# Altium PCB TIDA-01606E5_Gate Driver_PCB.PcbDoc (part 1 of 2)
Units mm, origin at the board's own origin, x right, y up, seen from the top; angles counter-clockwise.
Board outline 135 x 43 mm, 4 copper layers (Top Layer, GND, PWR, Bottom Layer), stack 1.59 mm thick; 184 components, 90 nets, 537 pads, 139 vias.
Unrouted connection lines stored in the file: 48.
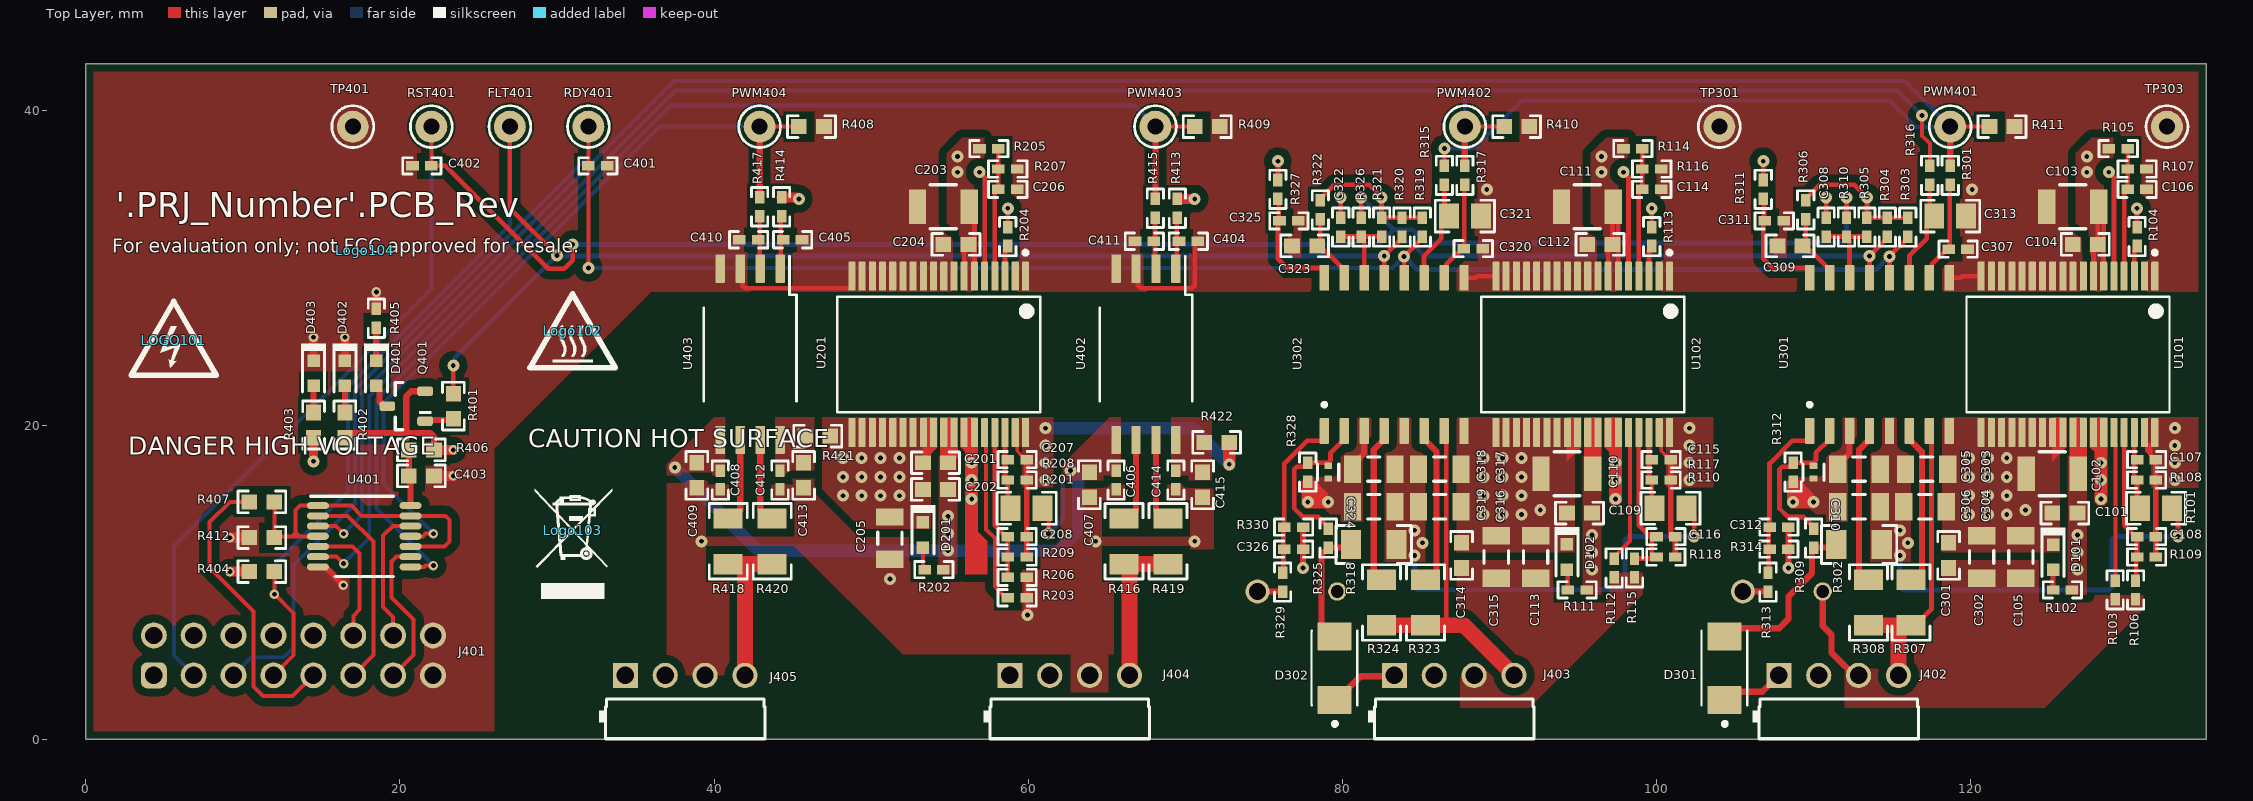
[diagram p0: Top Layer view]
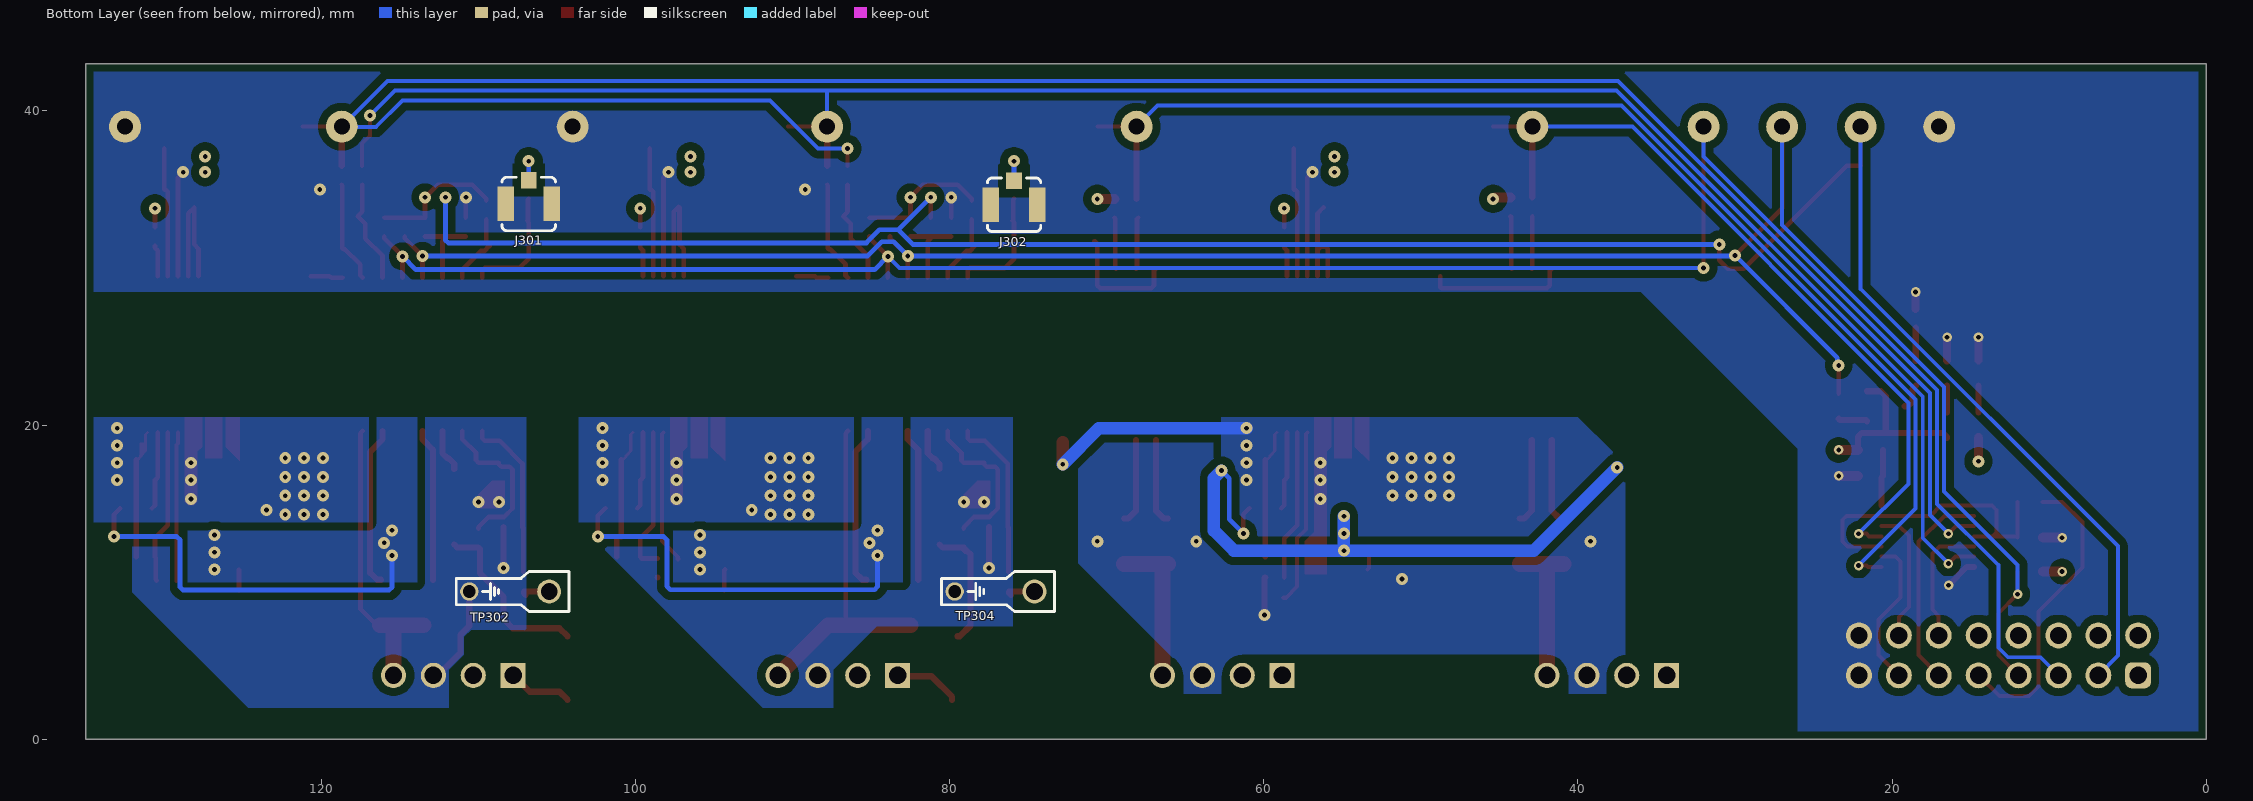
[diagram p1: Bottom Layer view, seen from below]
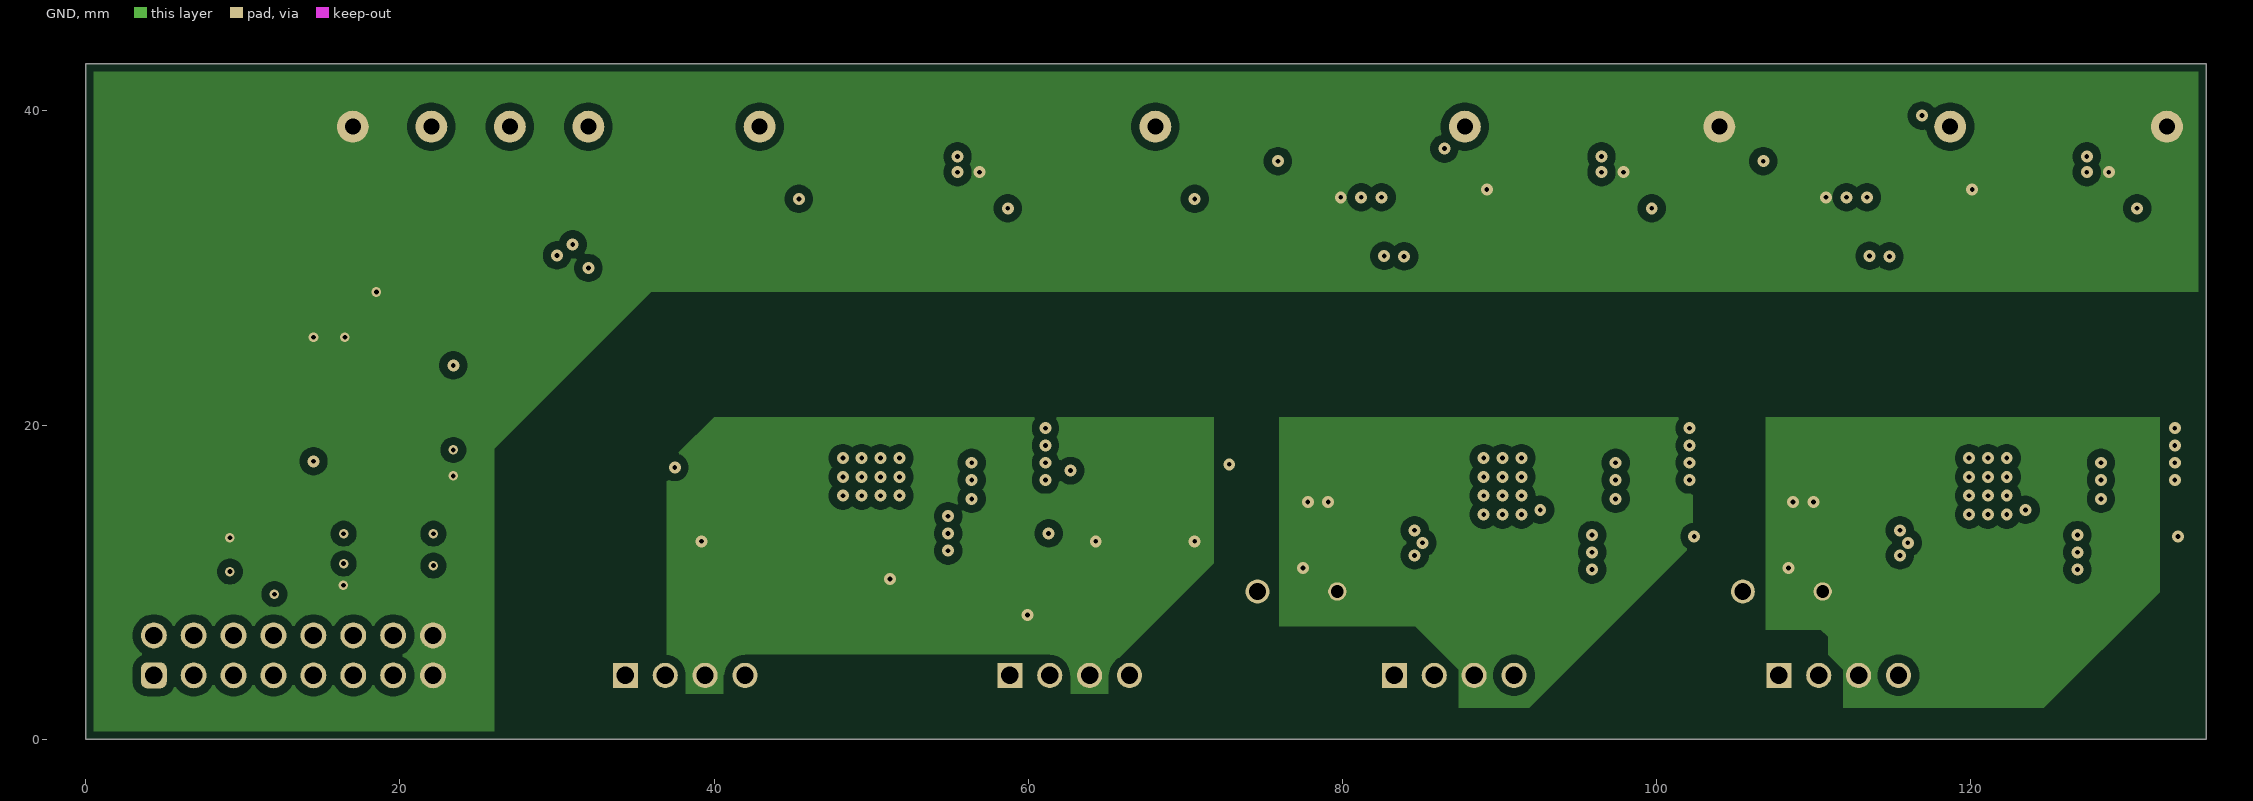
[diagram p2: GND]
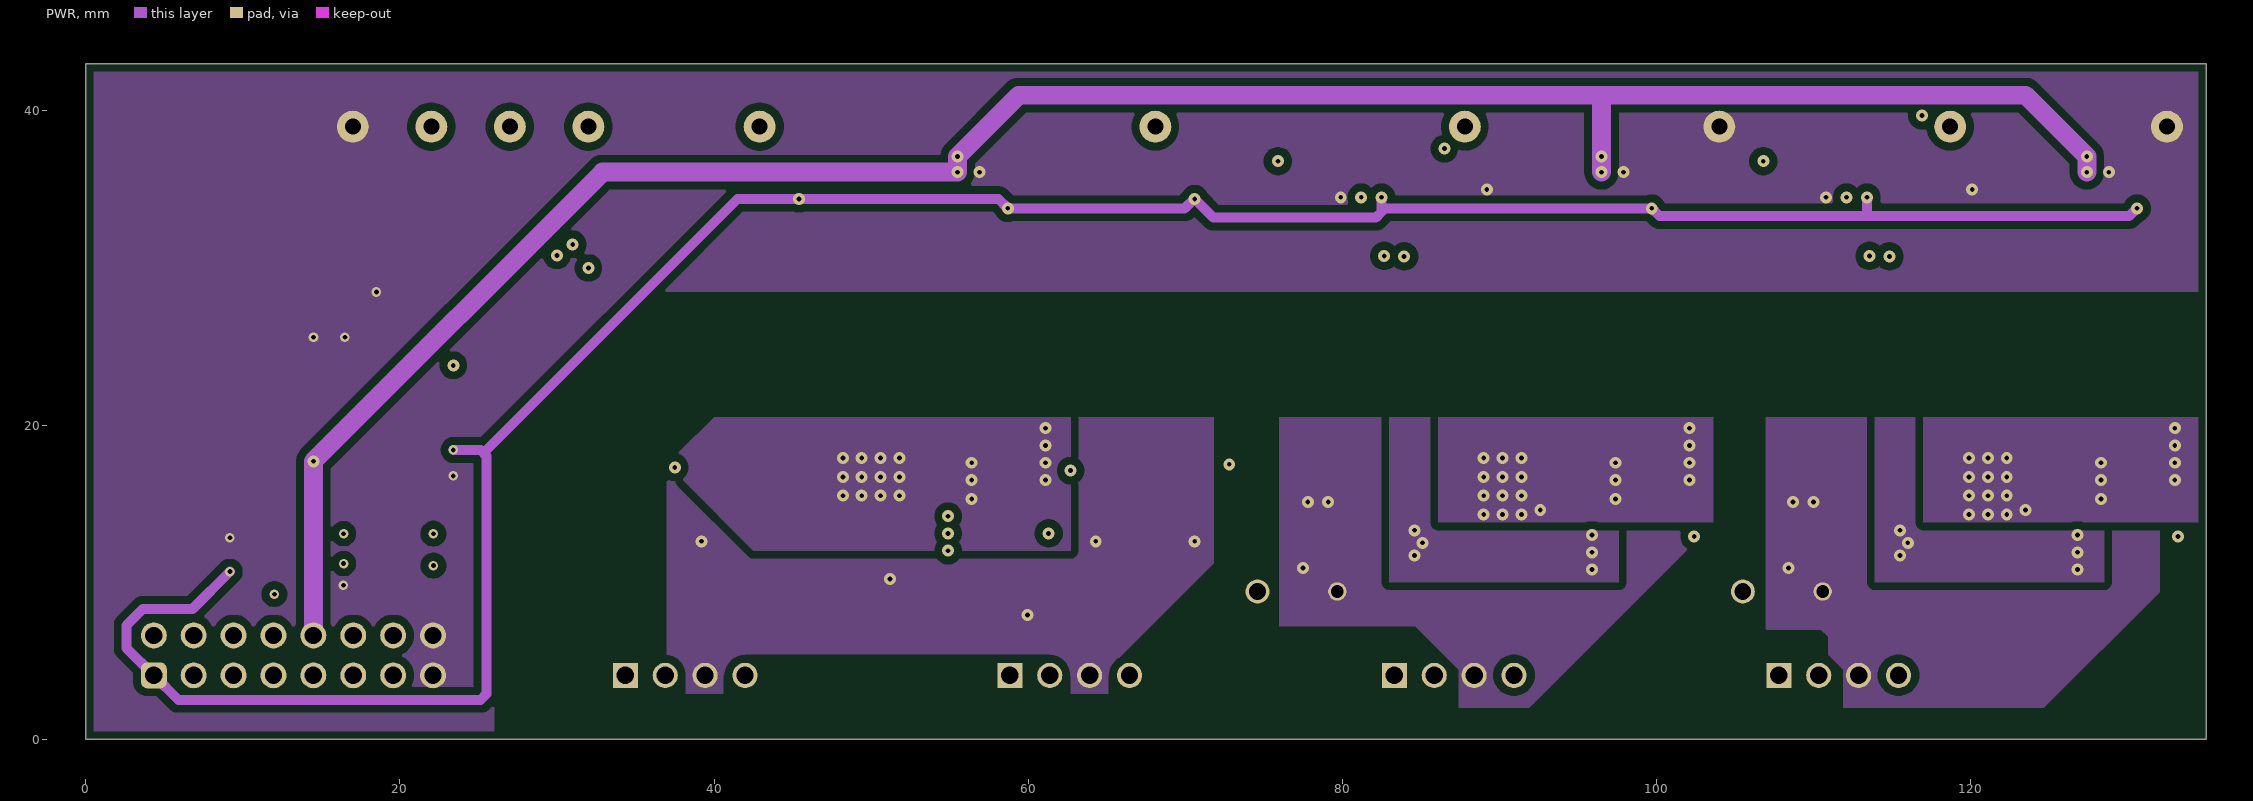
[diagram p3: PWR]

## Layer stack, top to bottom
Top Solder: solder mask 0.0102, Solder Resist, Dk 3.5
Top Layer: signal copper 0.0356
Dielectric1: core 0.5588, FR-4 High Tg, Dk 4.2
GND: signal copper 0.0356
Dielectric 2: prepreg 0.3302, FR-4 High Tg, Dk 4.2
PWR: signal copper 0.0356
Dielectric 3: core 0.5588, FR-4 High Tg, Dk 4.2
Bottom Layer: signal copper 0.0356
Bottom Solder: solder mask 0.0102, Solder Resist, Dk 3.5

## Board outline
0,0 135,0 135,43 0,43

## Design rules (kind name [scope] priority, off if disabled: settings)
AcuteAngle [All] p1: minimum=4.50000000000000E+0001 checktracksonly=FALSE
AssemblyTestPointUsage [All] p1: valid=2
Clearance Clearance_2 [InNetClass('HV') vs Not InNetClass('HV')] p1: gap=1.524 ignorepadtopadclearanceinfootprint=FALSE
Clearance Clearance_1 [InNetClass('MV') vs Not InNetClass('MV')] p2: gap=0.762 ignorepadtopadclearanceinfootprint=FALSE
Clearance Clearance_Keepouts [((IsTrack Or IsArc) And Not InPoly) And IsFree and IsKeepOut vs ((IsTrack Or IsArc) And Not InPoly) And IsFree and IsKeepOut] p3: gap=0 ignorepadtopadclearanceinfootprint=FALSE
Clearance Clearance_BoardEdge_MountingHoles [OnCopper and InComponentClass('Mounting Holes') vs IsKeepOut] p4: gap=1.016 ignorepadtopadclearanceinfootprint=FALSE except(0: Arc-Hole Track-Hole SMDPad-Hole THPad-Hole Via-Hole Fill-Hole Poly-Hole Region-Hole Text-Hole)
Clearance Clearance_BoardEdge_Poly [OnCopper and InPoly vs IsKeepOut] p5: gap=0.635 ignorepadtopadclearanceinfootprint=FALSE except(0: Arc-Hole Track-Hole SMDPad-Hole THPad-Hole Via-Hole Fill-Hole Poly-Hole Region-Hole Text-Hole)
Clearance Clearance_BoardEdge [OnCopper and Not InComponentClass('Logo') and not InComponentClass('FiducialMark') and not InRegion(1000,500,4000,800) and Not IsKeepout vs IsKeepOut] p6: gap=1.905 ignorepadtopadclearanceinfootprint=FALSE except(0: Arc-Hole Track-Hole SMDPad-Hole THPad-Hole Via-Hole Fill-Hole Poly-Hole Region-Hole Text-Hole)
Clearance Clearance_Poly [InPolygon] p7: gap=0.508 ignorepadtopadclearanceinfootprint=FALSE except(0: Arc-Hole Track-Hole SMDPad-Hole THPad-Hole Via-Hole Fill-Hole Poly-Hole Region-Hole Text-Hole)
Clearance [All] p8: gap=0.2 ignorepadtopadclearanceinfootprint=FALSE except(0: Arc-Hole Track-Hole SMDPad-Hole THPad-Hole Via-Hole Fill-Hole Poly-Hole Region-Hole Text-Hole)
ComponentClearance ComponentClearance_MountingHoles_FiducialMarks [InComponentClass('Mounting Holes') vs InComponentClass('FiducialMark')] p1: gap=0.508 collisioncheckmode=3 verticalgap=0.254 showdistances=FALSE
ComponentClearance ComponentClearance_Shunt [InComponentClass('Header') vs InComponentClass('Shunt')] p2: gap=0 collisioncheckmode=3 verticalgap=0 showdistances=FALSE
ComponentClearance ComponentClearance_Logo [InComponentClass('Logo')] p3: gap=0.127 collisioncheckmode=3 verticalgap=0.254 showdistances=FALSE
ComponentClearance ComponentClearance_ScrewToNut [(HasFootprint('NY PMS 440 0025 PH')) vs (HasFootprint('Keystone_1902C'))] p4: gap=0.508 collisioncheckmode=3 verticalgap=2540 showdistances=FALSE
ComponentClearance ComponentClearance_MountingHoles [InComponentClass('Mounting Holes')] p5: gap=0.508 collisioncheckmode=3 verticalgap=0.254 showdistances=FALSE
ComponentClearance ComponentClearance_SmallPassives [HasFootprint('0201*') or HasFootprint('0402*') or HasFootprint('0508') or HasFootprint('0603*') or HasFootprint('0612') or HasFootprint('0805*') or HasFootprint('0815*') or HasFootprint('0830*') or HasFootprint('1206*') or HasFootprint('1210*') or HasFootprint('1808*') or HasFootprint('1812*') or HasFootprint('1825*') or HasFootprint('2010*') or HasFootprint('2220*') or HasFootprint('2225*') or HasFootprint('2512*') or HasFootprint('2728*') or HasFootprint('3518*') vs HasFootprint('0201*') or HasFootprint('0402*') or HasFootprint('0508') or HasFootprint('0603*') or HasFootprint('0612') or HasFootprint('0805*') or HasFootprint('0815*') or HasFootprint('0830*') or HasFootprint('1206*') or HasFootprint('1210*') or HasFootprint('1808*') or HasFootprint('1812*') or HasFootprint('1825*') or HasFootprint('2010*') or HasFootprint('2220*') or HasFootprint('2225*') or HasFootprint('2512*') or HasFootprint('2728*') or HasFootprint('3518*')] p6: gap=0.508 collisioncheckmode=3 verticalgap=0.508 showdistances=FALSE
ComponentClearance ComponentClearance_THtoSMT [IsThruComponent vs IsSMTComponent] p7: gap=0.254 collisioncheckmode=3 verticalgap=0.254 showdistances=FALSE
ComponentClearance ComponentClearance_THtoTH [IsThruComponent vs IsThruComponent] p8: gap=0.254 collisioncheckmode=3 verticalgap=0.254 showdistances=FALSE
ComponentClearance [All] p9: gap=0.254 collisioncheckmode=3 verticalgap=0.254 showdistances=FALSE
DiffPairsRouting [All] p1: maxlimit=2.54 minlimit=0.254 mostfreqgap=0.254 toplayer_minwidth=0.381 toplayer_maxwidth=0.381 toplayer_prefwidth=0.381 midlayer1_minwidth=0.381 midlayer1_maxwidth=0.381 midlayer1_prefwidth=0.381 midlayer2_minwidth=0.381 midlayer2_maxwidth=0.381 midlayer2_prefwidth=0.381 bottomlayer_minwidth=0.381 bottomlayer_maxwidth=0.381 bottomlayer_prefwidth=0.381 maxuncoupledlength=25.4
FabricationTestPointUsage TestPointUsage [All] p1: valid=2 allowmultiple=FALSE
FabricationTestpoint Testpoint [All] p1: side=3 testpointundercomponent=TRUE minsize=1.016 maxsize=2.54 preferedsize=1.524 minholesize=0 maxholesize=1.016 preferedholesize=0.813 testpointgrid=0.025 allowsidetop=TRUE allowsidebottom=TRUE usegrid=TRUE gridtolerance=0
FanoutControl Fanout_LCC [IsLCC] p1: bgadir=Out bgaviamode=Centered fanoutstyle=Auto fanoutdirection=Alternating viagrid=0.025 // Fanout_LCC (Default Rule)
FanoutControl Fanout_BGA [IsBGA] p2: bgadir=Out bgaviamode=Centered fanoutstyle=Auto fanoutdirection=Alternating viagrid=0.025 // Fanout_BGA (Default Rule)
FanoutControl Fanout_Default [All] p4: bgadir=Out bgaviamode=Centered fanoutstyle=Auto fanoutdirection=Alternating viagrid=0.025 // Fanout_Default (Default Rule)
FanoutControl Fanout_Small [(CompPinCount < 5)] p5: bgadir=Out bgaviamode=Centered fanoutstyle=Auto fanoutdirection=OutThenIn viagrid=0.025 // Fanout_Small (Default Rule)
Height [All] p1: minheight=0 maxheight=76.2 prefheight=12.7
HoleSize [All] p1: absolutevalues=TRUE maxlimit=6.375 minlimit=0.178 maxpercent=80.000 minpercent=20.000
MinimumAnnularRing MinimumAnnularRing_ThermalPadVias [IsVia and InAnyComponent] p1: minimumring=0.15
MinimumAnnularRing [All] p2: minimumring=0.124
MinimumSolderMaskSliver MinimumSolderMaskSliver_Logo [InComponentClass('Logo') vs InComponentClass('Logo')] p1: minsoldermaskwidth=0.018
MinimumSolderMaskSliver [All] p2: minsoldermaskwidth=0.051
PlaneConnect [All] p1: planeconnectstyle=Direct reliefexpansion=0.254 reliefentries=4 reliefconductorwidth=0.254 reliefairgap=0.254
PolygonConnect PolygonConnect_15 [All vs IsNamedPolygon('C109_2') Or  IsNamedPolygon('C107_2') Or  IsNamedPolygon('HV') Or  IsNamedPolygon('Q203_5') Or  IsNamedPolygon('C107_2') Or  IsNamedPolygon('HS') Or  IsNamedPolygon('Q201_5') Or  IsNamedPolygon('Q203_5') Or  IsNamedPolygon('C106_2') Or  IsNamedPolygon('C108_2') Or  IsNamedPolygon('Vout') Or  IsNamedPolygon('Q203_5') Or  IsNamedPolygon('C108_2') Or  IsNamedPolygon('C113_2') Or  IsNamedPolygon('Q203_5') Or  IsNamedPolygon('Q201_5') Or  IsNamedPolygon('C107_2') Or  IsNamedPolygon('C102_1') Or  IsNamedPolygon('SGND') Or  IsNamedPolygon('GND') Or  IsNamedPolygon('SGND') Or  IsNamedPolygon('GND') Or  IsNamedPolygon('IN+') Or  IsNamedPolygon('IN+') Or  IsNamedPolygon('Q201_5') Or  IsNamedPolygon('Q201_5') Or  IsNamedPolygon('SGND') Or  IsNamedPolygon('SGND') Or  IsNamedPolygon('Vout') Or  IsNamedPolygon('Vout') Or  IsNamedPolygon('IN+') Or  IsNamedPolygon('GND') Or  IsNamedPolygon('IN+') Or  IsNamedPolygon('GND')] p1: connectstyle=Direct reliefconductorwidth=0.254 reliefentries=4 polygonreliefangle="90 Angle" airgapwidth=0.254
PolygonConnect PolygonConnect_14 [All vs IsNamedPolygon('C106_2') Or  IsNamedPolygon('C107_2') Or  IsNamedPolygon('C107_2') Or  IsNamedPolygon('C107_2') Or  IsNamedPolygon('C102_1') Or  IsNamedPolygon('Q203_5') Or  IsNamedPolygon('Vout') Or  IsNamedPolygon('Q203_5') Or  IsNamedPolygon('Q203_5') Or  IsNamedPolygon('Q201_5') Or  IsNamedPolygon('C108_2') Or  IsNamedPolygon('Q203_5') Or  IsNamedPolygon('HS') Or  IsNamedPolygon('HV') Or  IsNamedPolygon('C108_2') Or  IsNamedPolygon('Q201_5') Or  IsNamedPolygon('C109_2') Or  IsNamedPolygon('Q201_5') Or  IsNamedPolygon('Q201_5') Or  IsNamedPolygon('C113_2')] p2: connectstyle=Direct reliefconductorwidth=0.254 reliefentries=4 polygonreliefangle="90 Angle" airgapwidth=0.254
PolygonConnect PolygonConnect_13 [All vs IsNamedPolygon('C102_1') Or  IsNamedPolygon('HV') Or  IsNamedPolygon('C107_2') Or  IsNamedPolygon('C109_2') Or  IsNamedPolygon('C107_2') Or  IsNamedPolygon('C108_2') Or  IsNamedPolygon('C106_2') Or  IsNamedPolygon('C108_2') Or  IsNamedPolygon('C113_2') Or  IsNamedPolygon('C107_2')] p3: connectstyle=Direct reliefconductorwidth=0.254 reliefentries=4 polygonreliefangle="90 Angle" airgapwidth=0.254
PolygonConnect PolygonConnect_12 [All vs IsNamedPolygon('C107_2') Or  IsNamedPolygon('C113_2') Or  IsNamedPolygon('C106_2') Or  IsNamedPolygon('C107_2') Or  IsNamedPolygon('C107_2') Or  IsNamedPolygon('C102_1')] p4: connectstyle=Direct reliefconductorwidth=0.254 reliefentries=4 polygonreliefangle="90 Angle" airgapwidth=0.254
PolygonConnect PolygonConnect_11 [All vs IsNamedPolygon('C106_2') Or  IsNamedPolygon('C102_1') Or  IsNamedPolygon('C107_2') Or  IsNamedPolygon('C107_2') Or  IsNamedPolygon('C107_2')] p5: connectstyle=Direct reliefconductorwidth=0.254 reliefentries=4 polygonreliefangle="90 Angle" airgapwidth=0.254
PolygonConnect PolygonConnect_10 [All vs IsNamedPolygon('C106_2')] p6: connectstyle=Direct reliefconductorwidth=0.254 reliefentries=4 polygonreliefangle="90 Angle" airgapwidth=0.254
PolygonConnect PolygonConnect_9 [All vs IsNamedPolygon('C11_1') Or  IsNamedPolygon('Vin') Or  IsNamedPolygon('Vin') Or  IsNamedPolygon('5V') Or  IsNamedPolygon('D6_2') Or  IsNamedPolygon('Q3_3') Or  IsNamedPolygon('GND2') Or  IsNamedPolygon('GND2') Or  IsNamedPolygon('GND') Or  IsNamedPolygon('Q3_4') Or  IsNamedPolygon('12V5') Or  IsNamedPolygon('GND') Or  IsNamedPolygon('12V5') Or  IsNamedPolygon('D3_1')] p7: connectstyle=Direct reliefconductorwidth=0.254 reliefentries=4 polygonreliefangle="90 Angle" airgapwidth=0.254
PolygonConnect PolygonConnect_8 [All vs IsNamedPolygon('C11_1') Or  IsNamedPolygon('Vin') Or  IsNamedPolygon('12V5') Or  IsNamedPolygon('Q3_3') Or  IsNamedPolygon('GND2') Or  IsNamedPolygon('GND2') Or  IsNamedPolygon('5V') Or  IsNamedPolygon('Q3_4') Or  IsNamedPolygon('12V5')] p8: connectstyle=Direct reliefconductorwidth=0.254 reliefentries=4 polygonreliefangle="90 Angle" airgapwidth=0.254
PolygonConnect PolygonConnect_7 [All vs IsNamedPolygon('GND2') Or  IsNamedPolygon('GND2') Or  IsNamedPolygon('5V') Or  IsNamedPolygon('12V5') Or  IsNamedPolygon('12V5') Or  IsNamedPolygon('C11_1')] p9: connectstyle=Direct reliefconductorwidth=0.254 reliefentries=4 polygonreliefangle="90 Angle" airgapwidth=0.254
PolygonConnect PolygonConnect_6 [All vs IsNamedPolygon('GND2') Or  IsNamedPolygon('SGND') Or  IsNamedPolygon('GND1') Or  IsNamedPolygon('C901_1') Or  IsNamedPolygon('SGND') Or  IsNamedPolygon('GND2') Or  IsNamedPolygon('GND1')] p10: connectstyle=Direct reliefconductorwidth=0.254 reliefentries=4 polygonreliefangle="90 Angle" airgapwidth=0.254
PolygonConnect PolygonConnect_5 [All vs IsNamedPolygon('GND1') Or  IsNamedPolygon('GND1')] p11: connectstyle=Direct reliefconductorwidth=0.254 reliefentries=4 polygonreliefangle="90 Angle" airgapwidth=0.254
PolygonConnect PolygonConnect_4 [All vs IsNamedPolygon('C21_1') Or  IsNamedPolygon('C5_1') Or  IsNamedPolygon('C12_2') Or  IsNamedPolygon('C2_2') Or  IsNamedPolygon('C13_1') Or  IsNamedPolygon('C28_1') Or  IsNamedPolygon('C6_1') Or  IsNamedPolygon('GND') Or  IsNamedPolygon('GND2') Or  IsNamedPolygon('C14_1') Or  IsNamedPolygon('C13_1') Or  IsNamedPolygon('Q1_3') Or  IsNamedPolygon('C14_1') Or  IsNamedPolygon('C5_1') Or  IsNamedPolygon('GND2') Or  IsNamedPolygon('C28_1') Or  IsNamedPolygon('D5_2') Or  IsNamedPolygon('D6_2') Or  IsNamedPolygon('D2_1') Or  IsNamedPolygon('C12_2') Or  IsNamedPolygon('D2_1') Or  IsNamedPolygon('C4_1') Or  IsNamedPolygon('C4_1') Or  IsNamedPolygon('C2_2') Or  IsNamedPolygon('GND') Or  IsNamedPolygon('C33_1') Or  IsNamedPolygon('C9_1')] p12: connectstyle=Direct reliefconductorwidth=0.254 reliefentries=4 polygonreliefangle="90 Angle" airgapwidth=0.254
PolygonConnect PolygonConnect_3 [All vs IsNamedPolygon('C28_1') Or  IsNamedPolygon('C12_2') Or  IsNamedPolygon('C28_1') Or  IsNamedPolygon('C9_1') Or  IsNamedPolygon('D5_2') Or  IsNamedPolygon('C12_2') Or  IsNamedPolygon('C2_2') Or  IsNamedPolygon('C14_1') Or  IsNamedPolygon('C4_1') Or  IsNamedPolygon('C14_1') Or  IsNamedPolygon('D6_2') Or  IsNamedPolygon('GND2') Or  IsNamedPolygon('Q1_3') Or  IsNamedPolygon('C5_1') Or  IsNamedPolygon('D2_1') Or  IsNamedPolygon('C4_1') Or  IsNamedPolygon('C13_1') Or  IsNamedPolygon('C5_1') Or  IsNamedPolygon('C13_1') Or  IsNamedPolygon('C33_1') Or  IsNamedPolygon('D2_1') Or  IsNamedPolygon('GND') Or  IsNamedPolygon('GND') Or  IsNamedPolygon('GND2') Or  IsNamedPolygon('C2_2') Or  IsNamedPolygon('C6_1') Or  IsNamedPolygon('C21_1')] p13: connectstyle=Direct reliefconductorwidth=0.254 reliefentries=4 polygonreliefangle="90 Angle" airgapwidth=0.254
PolygonConnect PolygonConnect_2 [All vs IsNamedPolygon('C21_1') Or  IsNamedPolygon('C4_1') Or  IsNamedPolygon('D5_2') Or  IsNamedPolygon('C5_1') Or  IsNamedPolygon('C14_1') Or  IsNamedPolygon('C13_1') Or  IsNamedPolygon('C4_1') Or  IsNamedPolygon('C33_1') Or  IsNamedPolygon('C12_2') Or  IsNamedPolygon('D2_1') Or  IsNamedPolygon('C2_2') Or  IsNamedPolygon('C28_1') Or  IsNamedPolygon('C12_2') Or  IsNamedPolygon('D2_1') Or  IsNamedPolygon('C5_1') Or  IsNamedPolygon('Q1_3') Or  IsNamedPolygon('GND') Or  IsNamedPolygon('D6_2') Or  IsNamedPolygon('C6_1') Or  IsNamedPolygon('C2_2') Or  IsNamedPolygon('C14_1') Or  IsNamedPolygon('C28_1') Or  IsNamedPolygon('C13_1') Or  IsNamedPolygon('C9_1') Or  IsNamedPolygon('GND')] p14: connectstyle=Direct reliefconductorwidth=0.254 reliefentries=4 polygonreliefangle="90 Angle" airgapwidth=0.254
PolygonConnect PolygonConnect_1 [All vs IsNamedPolygon('C28_1') Or  IsNamedPolygon('D5_2') Or  IsNamedPolygon('C5_1') Or  IsNamedPolygon('C5_1') Or  IsNamedPolygon('D2_1') Or  IsNamedPolygon('C21_1') Or  IsNamedPolygon('C9_1') Or  IsNamedPolygon('C4_1') Or  IsNamedPolygon('C14_1') Or  IsNamedPolygon('C28_1') Or  IsNamedPolygon('C6_1') Or  IsNamedPolygon('C12_2') Or  IsNamedPolygon('C33_1') Or  IsNamedPolygon('C4_1') Or  IsNamedPolygon('C13_1') Or  IsNamedPolygon('C12_2') Or  IsNamedPolygon('D6_2') Or  IsNamedPolygon('C2_2') Or  IsNamedPolygon('C14_1') Or  IsNamedPolygon('D2_1') Or  IsNamedPolygon('C2_2') Or  IsNamedPolygon('C13_1')] p15: connectstyle=Direct reliefconductorwidth=0.254 reliefentries=4 polygonreliefangle="90 Angle" airgapwidth=0.254
PolygonConnect [All] p16: connectstyle=Direct reliefconductorwidth=0.254 reliefentries=4 polygonreliefangle="90 Angle" airgapwidth=0.254
RoutingVias ThermalPadVias [IsVia and InAnyComponent] p1: holewidth=0.2 width=0.5 viastyle="Through Hole" minholewidth=0.2 minwidth=0.5 maxholewidth=0.33 maxwidth=0.6
RoutingVias [All] p2: holewidth=0.406 width=0.864 viastyle="Through Hole" minholewidth=0.2 minwidth=0.508 maxholewidth=1.016 maxwidth=1.651
SilkToBoardRegionClearance [Not ((IsComment or IsDesignator) And (Hide <> 'False')) and not InRegion(1000,500,4000,800)] p1:
SilkToSilkClearance SilkToSilkClearance_Pb-FreeLogo [(HasFootprint('Pb-Free_Overlay_Medium') OR HasFootprint('Pb-Free_Overlay_Small')) vs (HasFootprint('Pb-Free_Overlay_Medium') OR HasFootprint('Pb-Free_Overlay_Small'))] p1: silktosilkclearance=0
SilkToSilkClearance [All] p2: silktosilkclearance=0.025
SilkToSolderMaskClearance "Silk to Solder Mask Opening" [All] p1: minsilkscreentomaskgap=0.025 clearancetoexposedcopper=FALSE
SolderMaskExpansion [All] p1: expansion=0.05 istentingtop=FALSE
Width [All] p1: maxlimit=2.54 minlimit=0.152 preferedwidth=0.254 checkconnectedcopper=TRUE
14 further rules are at their usual default settings.

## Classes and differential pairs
component class "TIDA-01606E4_Gate Driver_Isolated Gate Driver_Pg4": C401 C402 C403 C404 C405 C406 C407 C408 C409 C410 C411 C412 C413 C414 C415 D401 D402 D403 FLT401 J401 J402 J403 J404 J405 PWM401 PWM402 PWM403 PWM404 Q401 R401 R402 R403 R404 R405 R406 R407 R408 R409 R410 R411 R412 R413 R414 R415 R416 R417 R418 R419 R420 R421 R422 RDY401 RST401 TP401 U401 U402 U403
component class "TIDA-01606E4_Gate Driver_Gate Drive power supply_Pg2": C201 C202 C203 C204 C205 C206 C207 C208 D201 R201 R202 R203 R204 R205 R206 R207 R208 R209 U201
component class "TIDA-01606E4_Gate Driver_Gate Drive power supply_Pg1": C101 C102 C103 C104 C105 C106 C107 C108 C109 C110 C111 C112 C113 C114 C115 C116 D101 D102 LOGO101 Logo102 Logo103 Logo104 R101 R102 R103 R104 R105 R106 R107 R108 R109 R110 R111 R112 R113 R114 R115 R116 R117 R118 U101 U102
component class "TIDA-01606E4_Gate Driver_Isolated Gate Driver_Pg3": C301 C302 C303 C304 C305 C306 C307 C308 C309 C310 C311 C312 C313 C314 C315 C316 C317 C318 C319 C320 C321 C322 C323 C324 C325 C326 D301 D302 J301 J302 R301 R302 R303 R304 R305 R306 R307 R308 R309 R310 R311 R312 R313 R314 R315 R316 R317 R318 R319 R320 R321 R322 R323 R324 R325 R326 R327 R328 R329 R330 TP301 TP302 TP303 TP304 U301 U302
component class Header: J401 J402 J403 J404 J405

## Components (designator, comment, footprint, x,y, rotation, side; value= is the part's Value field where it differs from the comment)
C101 "CGA3E2X7R1H104K080AA" 0603 126,14.4 r180 top value=0.1uF
C102 "C3225X7R1H225K250AB" 1210_280 125.2,16.9 r180 top value=2.2uF
C103 "C3225X7R1H225K250AB" 1210_280 126.5,33.9 r180 top value=2.2uF
C104 "CGA3E2X7R1H104K080AA" 0603 127.3,31.5 r180 top value=0.1uF
C105 "GRM31CR71A226KE15L" 1206_180L 123.2,11.6 r90 top value=22uF
C106 "GRM155R71A104KA01D" 0402 130.6,35 r0 top value=0.1uF
C107 "GRM155R71H331KA01D" 0402 131.2,17.8 r180 top value=330pF
C108 "GRM155R71H331KA01D" 0402 131.2,12.9 r180 top value=330pF
C109 "CGA3E2X7R1H104K080AA" 0603 95.1,14.4 r180 top value=0.1uF
C110 "C3225X7R1H225K250AB" 1210_280 94.3,16.9 r180 top value=2.2uF
C111 "C3225X7R1H225K250AB" 1210_280 95.6,33.9 r180 top value=2.2uF
C112 "CGA3E2X7R1H104K080AA" 0603 96.4,31.5 r180 top value=0.1uF
C113 "GRM31CR71A226KE15L" 1206_180L 92.3,11.6 r90 top value=22uF
C114 "GRM155R71A104KA01D" 0402 99.7,35 r0 top value=0.1uF
C115 "GRM155R71H331KA01D" 0402 100.3,17.8 r180 top value=330pF
C116 "GRM155R71H331KA01D" 0402 100.6,12.9 r180 top value=330pF
C201 "CGA3E2X7R1H104K080AA" 0603 54.1,17.6 r180 top value=0.1uF
C202 "UMK107AB7105KA-T" 0603 54.1,15.9 r180 top value=1uF
C203 "C3225X7R1H225K250AB" 1210_280 54.6,33.9 r180 top value=2.2uF
C204 "CGA3E2X7R1H104K080AA" 0603 55.4,31.5 r180 top value=0.1uF
C205 "C3216X7S1A156M160AC" 1206_180L 51.2,12.8 r90 top value=15uF
C206 "GRM155R71A104KA01D" 0402 58.7,35 r0 top value=0.1uF
C207 "GRM155R71H331KA01D" 0402 59.3,17.8 r180 top value=330pF
C208 "GRM155R71H331KA01D" 0402 59.3,12.9 r180 top value=330pF
C301 "0603ZC104KAT2A" 0603 118.6,11.7 r90 top value=0.1uF
C302 "GRM31CR71A226KE15L" 1206_180L 120.7,11.6 r270 top value=22uF
C303 "GRM319R71H104KA01D" 1206L 117.2,17.2 r180 top value=0.1uF
C304 "GRM31MR71H105KA88L" 1206L 117.1,14.8 r180 top value=1uF
C305 "GRM319R71H104KA01D" 1206L 112.9,17.2 r0 top value=0.1uF
C306 "GRM31CR61H106KA12L" 1206_180L 112.9,14.8 r0 top value=10uF
C307 "GRM1555C1H101JA01D" 0402 119.2,31.2 r0 top value=100pF
C308 "GRM1555C1H101JA01D" 0402 110.8,32.6 r90 top value=100pF
C309 "0603ZC104KAT2A" 0603 108.5,31.4 r0 top value=0.1uF
C310 "GCM155R72A331KA37D" FP-GCM155R72A331KA37D_0402-MFG 110,17 r90 top
C311 "885012205008" 0402 107.5,33 r180 top value=2200pF
C312 "GRM155R71A104KA01D" 0402 107.8,13.5 r0 top value=0.1uF
C313 "GRM2165C1H101JA01D" 0805_HV 118.7,33.3 r0 top value=100pF
C314 "0603ZC104KAT2A" 0603 87.6,11.7 r90 top value=0.1uF
C315 "GRM31CR71A226KE15L" 1206_180L 89.8,11.6 r270 top value=22uF
C316 "GRM319R71H104KA01D" 1206L 86.2,14.8 r180 top value=0.1uF
C317 "GRM31MR71H105KA88L" 1206L 86.2,17.2 r180 top value=1uF
C318 "GRM319R71H104KA01D" 1206L 82,17.2 r0 top value=0.1uF
C319 "GRM31CR61H106KA12L" 1206_180L 82,14.8 r0 top value=10uF
C320 "GRM1555C1H101JA01D" 0402 88.334,31.235 r0 top value=100pF
C321 "GRM2165C1H101JA01D" 0805_HV 87.8,33.3 r0 top value=100pF
C322 "GRM1555C1H101JA01D" 0402 79.9,32.6 r90 top value=100pF
C323 "0603ZC104KAT2A" 0603 77.6,31.4 r0 top value=0.1uF
C324 "GCM155R72A331KA37D" FP-GCM155R72A331KA37D_0402-MFG 79.1,17 r90 top
C325 "885012205008" 0402 76.6,33 r180 top value=2200pF
C326 "GRM155R71A104KA01D" 0402 76.9,12.1 r0 top value=0.1uF
C401 "C0402C101J3GACTU" 0402 32.6,36.5 r0 top value=100pF
C402 "C0402C101J3GACTU" 0402 21.4,36.5 r180 top value=100pF
C403 "885012206095" 0603 21.368,16.764 r0 top value=0.1uF
C404 "GRM155R61H104ME14D" 0402 70.2,31.7 r0 top value=0.1uF
C405 "GRM155R61H104ME14D" 0402 45,31.8 r0 top value=0.1uF
C406 "GRM155R61H104ME14D" 0402 65.6,16.5 r270 top value=0.1uF
C407 "C1608X5R1E106M080AC" 0603 63.9,16.2 r270 top value=10uF
C408 "GRM155R61H104ME14D" 0402 40.4,16.5 r270 top value=0.1uF
C409 "C1608X5R1E106M080AC" 0603 38.9,16.8 r270 top value=10uF
C410 "GRM1555C1H101JA01D" 0402 42.2,31.8 r180 top value=100pF
C411 "GRM1555C1H101JA01D" 0402 67.4,31.7 r180 top value=100pF
C412 "GRM155R61H104ME14D" 0402 44.2,16.5 r270 top value=0.1uF
C413 "C1608X5R1E106M080AC" 0603 45.7,16.8 r270 top value=10uF
C414 "GRM155R61H104ME14D" 0402 69.4,16.5 r270 top value=0.1uF
C415 "C1608X5R1E106M080AC" 0603 71.1,16.2 r270 top value=10uF
D101 "150060GS75000" WL-SMCW_GREEN 125.249,11.575 r270 top value=Green
D102 "150060GS75000" WL-SMCW_GREEN 94.3,11.6 r270 top value=Green
D201 "150060GS75000" WL-SMCW_GREEN 53.299,13 r270 top value=Green
D301 "US1Q-TP" FP-US1Q-TP_SMA-MFG 104.325,4.525 r90 top
D302 "US1Q-TP" FP-US1Q-TP_SMA-MFG 79.5,4.525 r90 top
D401 "150060RS75000" WL-SMCW_RED 18.5,23.3 r270 top value=Red
D402 "150060GS75000" WL-SMCW_GREEN 16.5,23.3 r270 top value=Green
D403 "150060GS75000" WL-SMCW_GREEN 14.5,23.3 r270 top value=Green
FLT401 "5002" Keystone5002 27,39 r90 top
J301 "U.FL-R-SMT-1(01)" CONN_UFL-R-SMT-1 106.8,34.075 r270 bottom
J302 "U.FL-R-SMT-1(01)" CONN_UFL-R-SMT-1 75.9,34.025 r270 bottom
J401 "61301621021" Wurth_61301621021 13.22,5.334 r90 top
J402 "61300411021" Wurth_61300411021 111.6,4.064 r0 top
J403 "61300411021" Wurth_61300411021 87.12,4.064 r0 top
J404 "61300411021" Wurth_61300411021 62.64,4.064 r0 top
J405 "61300411021" Wurth_61300411021 38.16,4.064 r0 top
LOGO101 "DANGER HIGH VOLTAGE" IEC_HighVoltage_Small 5.6,25.4 r0 top
Logo102 "CAUTION HOT SURFACE" IEC_HotSurface_Small 31,26 r0 top
Logo103 "WEEE logo" WEEE_Minimum 31,13.3 r0 top
Logo104 "FCC disclaimer" FCC_disclaimer 17.786,31.143 r0 top
PWM401 "5002" Keystone5002 118.7,39 r90 top
PWM402 "5002" Keystone5002 87.8,39 r90 top
PWM403 "5002" Keystone5002 68.1,39 r90 top
PWM404 "5002" Keystone5002 42.9,39 r90 top
Q401 "BC856A-7-F" SOT-23 20.4,21.2 r180 top value="65 V"
R101 "RT0805BRD0765K7L" 0805_HV 131.8,14.7 r0 top value=65.7k
R102 "CRCW04022K21FKED" 0402 125.85,9.5 r0 top value=2.21k
R103 "ERJ-2RKF4700X" 0402 129.2,9.5 r270 top value=470
R104 "CRCW0402100KFKED" 0402 130.6,32 r270 top value=100k
R105 "CRCW040210K0FKED" 0402 129.4,37.6 r180 top value=10.0k
R106 "CRCW040230K0FKED" 0402 130.5,9.5 r270 top value=30.0k
R107 "CRCW04021K21FKED" 0402 130.6,36.3 r180 top value=1.21k
R108 "CRCW040210K0FKED" 0402 131.2,16.5 r180 top value=10.0k
R109 "MCR01MZPF4992" 0402 131.2,11.6 r180 top value=49.9k
R110 "RT0805BRD0765K7L" 0805_HV 100.9,14.7 r0 top value=65.7k
R111 "CRCW04022K21FKED" 0402 94.95,9.5 r0 top value=2.21k
R112 "ERJ-2RKF4700X" 0402 97.3,10.9 r270 top value=470
R113 "CRCW0402100KFKED" 0402 99.7,32 r270 top value=100k
R114 "CRCW040210K0FKED" 0402 98.5,37.6 r180 top value=10.0k
R115 "CRCW040230K0FKED" 0402 98.6,10.9 r270 top value=30.0k
R116 "CRCW04021K21FKED" 0402 99.7,36.3 r180 top value=1.21k
R117 "CRCW040210K0FKED" 0402 100.3,16.5 r180 top value=10.0k
R118 "MCR01MZPF4992" 0402 100.6,11.6 r180 top value=49.9k
R201 "RT0805BRD0765K7L" 0805_HV 59.9,14.7 r0 top value=65.7k
R202 "CRCW04022K21FKED" 0402 54,10.8 r0 top value=2.21k
R203 "ERJ-2RKF4700X" 0402 59.3,9 r0 top value=470
R204 "CRCW0402100KFKED" 0402 58.7,32 r270 top value=100k
R205 "CRCW040210K0FKED" 0402 57.5,37.6 r180 top value=10.0k
R206 "CRCW040230K0FKED" 0402 59.3,10.3 r0 top value=30.0k
R207 "CRCW04021K21FKED" 0402 58.7,36.3 r180 top value=1.21k
R208 "CRCW040210K0FKED" 0402 59.3,16.5 r180 top value=10.0k
R209 "MCR01MZPF4992" 0402 59.3,11.6 r180 top value=49.9k
R301 "CRCW0402100RFKED" 0402 118.7,35.9 r270 top value=100
R302 "RC1206FR-0715KL" 1206 112.9,12.4 r0 top value=15.0k
R303 "CRCW040210K0FKED" 0402 116,32.6 r90 top value=10.0k
R304 "CRCW040210K0FKED" 0402 114.7,32.6 r90 top value=10.0k
R305 "CRCW040210K0FKED" 0402 113.4,32.6 r90 top value=10.0k
R306 "CRCW040210R0FKED" 0402 109.5,33.7 r90 top value=10.0
R307 "CRCW12062R00JNEA" 1206 116.2,8.7 r270 top value=2.0
R308 "CRCW12062R00JNEA" 1206 113.5,8.7 r270 top value=2.0
R309 "ERJ2RKF1802X" 0402 110,12.8 r270 top value=18.0k
R310 "CRCW0402100RFKED" 0402 112.1,32.6 r270 top value=100
R311 "CRCW040220K0FKED" 0402 106.8,35 r270 top value=20.0k
R312 "CRCW04022K00FKED" 0402 108.7,17 r90 top value=2.00k
R313 "CRCW04020000Z0ED" 0402 107.1,10 r270 top value=0
R314 "CRCW04026K19FKED" 0402 107.8,12.1 r180 top value=6.19k
R315 "CRCW0402100RFKED" 0402 86.5,35.9 r90 top value=100
R316 "CRCW0402100RFKED" 0402 117.4,35.9 r270 top value=100
R317 "CRCW0402100RFKED" 0402 87.8,35.9 r90 top value=100
R318 "RC1206FR-0715KL" 1206 82,12.4 r0 top value=15.0k
R319 "CRCW040210K0FKED" 0402 85.1,32.6 r90 top value=10.0k
R320 "CRCW040210K0FKED" 0402 83.8,32.6 r90 top value=10.0k
R321 "CRCW040210K0FKED" 0402 82.5,32.6 r90 top value=10.0k
R322 "CRCW040210R0FKED" 0402 78.6,33.7 r90 top value=10.0
R323 "CRCW12062R00JNEA" 1206 85.3,8.7 r270 top value=2.0
R324 "CRCW12062R00JNEA" 1206 82.5,8.7 r270 top value=2.0
R325 "ERJ2RKF1802X" 0402 79.1,12.8 r270 top value=18.0k
R326 "CRCW0402100RFKED" 0402 81.2,32.6 r270 top value=100
R327 "CRCW040220K0FKED" 0402 75.9,35 r270 top value=20.0k
R328 "CRCW04022K00FKED" 0402 77.8,17 r90 top value=2.00k
R329 "CRCW04020000Z0ED" 0402 76.2,10 r270 top value=0
R330 "CRCW04026K19FKED" 0402 76.9,13.5 r180 top value=6.19k
R401 "ERJ-3EKF2002V" 0603 23.4,21.2 r270 top value=20.0k
R402 "RC0603FR-07620RL" 0603 16.5,20 r270 top value=620
R403 "RT0603BRD072K18L" 0603 14.5,20 r270 top value=2.18k
R404 "CRCW060310K0FKEA" 0603 11.208,10.668 r180 top value=10.0k
R405 "CRCW0402120RJNED" 0402 18.5,26.8 r270 top value=120
R406 "RC0603FR-0710RL" 0603 21.368,18.415 r180 top value=10.0
R407 "ERJ-3GEY0R00V" 0603 11.208,15.113 r0 top value=0
R408 "CRCW060310K0FKEA" 0603 46.2,39 r180 top value=10.0k
R409 "CRCW060310K0FKEA" 0603 71.4,39 r180 top value=10.0k
R410 "CRCW060310K0FKEA" 0603 91.1,39 r180 top value=10.0k
R411 "CRCW060310K0FKEA" 0603 122,39 r180 top value=10.0k
R412 "CRCW060310K0FKEA" 0603 11.208,12.827 r0 top value=10.0k
R413 "CRCW040210R0FKED" 0402 69.5,33.8 r270 top value=10.0
R414 "CRCW040210R0FKED" 0402 44.3,33.9 r270 top value=10.0
R415 "CRCW0402100RFKED" 0402 68.1,33.8 r270 top value=100
R416 "RC1206FR-073R3L" 1206 66.1,12.6 r270 top value=3.30
R417 "CRCW0402100RFKED" 0402 42.9,33.9 r270 top value=100
R418 "RC1206FR-073R3L" 1206 40.9,12.6 r270 top value=3.30
R419 "RC1206FR-073R3L" 1206 68.9,12.6 r270 top value=3.30
R420 "RC1206FR-073R3L" 1206 43.7,12.6 r270 top value=3.30
R421 "PMR03EZPJ000" 0603 46.6,19.3 r0 top value=0
R422 "PMR03EZPJ000" 0603 72,18.9 r0 top value=0
RDY401 "5002" Keystone5002 32,39 r90 top
RST401 "5002" Keystone5002 22,39 r90 top
TP301 "5001" Keystone5001 104,39 r90 top
TP302 "GNDP" TESTPOINT_PIGTAIL 105.5,9.4 r270 bottom
TP303 "5001" Keystone5001 132.5,39 r90 top
TP304 "GNDP" TESTPOINT_PIGTAIL 74.6,9.4 r270 bottom
TP401 "5001" Keystone5001 17,39 r90 top
U101 "UCC14240DWNQ1" DWN0036-MFG 126.2,24.5 r270 top
U102 "UCC14240DWNQ1" DWN0036-MFG 95.3,24.5 r270 top
U201 "UCC14240DWNQ1" DWN0036-MFG 54.3,24.5 r270 top
U301 "UCC21710QDWQ1" DW0016B_HV 114.2,24.5 r90 top
U302 "UCC21710QDWQ1" DW0016B_HV 83.3,24.5 r90 top
U401 "SN74LVC126APWR" PW0014A_N 17.726,12.918 r0 top
U402 "UCC5320SCDWV" DWV0008A 67.5,24.5 r270 top
U403 "UCC5320SCDWV" DWV0008A 42.3,24.5 r270 top

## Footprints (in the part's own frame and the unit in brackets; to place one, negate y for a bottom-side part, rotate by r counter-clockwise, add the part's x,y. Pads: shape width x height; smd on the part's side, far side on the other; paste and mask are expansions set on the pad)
0402 [mm] "0402 from SM-752 data"
  rect 0.8x0.6 smd: 1(-0.6,0) 2(0.6,0)
  silkscreen extent -1.22,-0.52 1.22,0.52, body extent -0.55,-0.3 0.55,0.3, height 0.6
0603 [mm] "0603 from SM-752 data"
  rect 1x0.95 smd: 1(-0.8,0) 2(0.8,0)
  silkscreen extent -1.52,-0.69 1.52,0.69, body extent -0.87,-0.47 0.87,0.47, height 1
0805_HV [mil] "0805 with 30mil clearance between pads"
  rect 50x63 smd: 1(-40,0) 2(40,0)
  silkscreen extent -74,-40 74,40, body extent -43,-29 43,29, height 57
1206 [mm] "1206 from SM-752 data"
  rect 1.3x1.85 smd: 1(-1.45,0) 2(1.45,0)
  silkscreen extent -2.4,-1.21 2.4,1.21, body extent -1.7,-0.9 1.7,0.9, height 1.35
1206_180L [mm] "1206_180"
  rect 1.1x1.75 smd: 1(-1.35,0) 2(1.35,0)
  silkscreen extent -0.4,-0.77 0.4,0.77, body extent -1.75,-0.95 1.75,0.95, height 1.8
1206L [mm] "1206 from SM-752 data"
  rect 1.1x1.75 smd: 1(-1.35,0) 2(1.35,0)
  silkscreen extent -0.4,-0.77 0.4,0.77, body extent -1.7,-0.9 1.7,0.9, height 1.35
1210_280 [mm] "SMD, 2-Leads, Body 3.6x2.8mm, Height 2.8mm"
  rect 1.1x2.2 smd: 1(-1.65,0) 2(1.65,0)
  silkscreen extent -0.84,-1.4 0.84,1.4, body extent -1.8,-1.4 1.8,1.4, height 2.8
CONN_UFL-R-SMT-1 [mm] "Hirose recommended land pattern http://www.hirose.co.jp/cataloge_hp/e32119372.pdf 2009.2"
  rect 1.05x1 smd paste-0.1 mask-0.1: 1(-1.525,0)
  rect 2.2x1.05 smd paste-2 mask-2: 2(0,1.475) 3(0,-1.475)
  rect 2x0.9 on Bottom Solder: 2(0,1.5) 3(0,-1.5)
  rect 2x0.9 on Bottom Paste: 2(0,1.5) 3(0,-1.5)
  silkscreen extent -1.7,-1.7 1.7,1.7, body extent -1.55,-1.5 1.55,1.5, height 1.27
DW0016B_HV [mm] "SOIC-16, HV/isolation option"
  rrect17% 1.65x0.6 smd: 1(-4.875,4.445) 2(-4.875,3.175) 3(-4.875,1.905) 4(-4.875,0.635) 5(-4.875,-0.635) 6(-4.875,-1.905) 7(-4.875,-3.175) 8(-4.875,-4.445) 9(4.875,-4.445) 10(4.875,-3.175) 11(4.875,-1.905) 12(4.875,-0.635) 13(4.875,0.635) 14(4.875,1.905) 15(4.875,3.175) 16(4.875,4.445)
  body extent -5.17,-5.15 5.17,5.15, height 2.59
DWN0036-MFG [mm]
  rrect22% 1.85x0.45 smd paste+0 mask+0: 1(-4.975,5.525) 2(-4.975,4.875) 3(-4.975,4.225) 4(-4.975,3.575) 5(-4.975,2.925) 6(-4.975,2.275) 7(-4.975,1.625) 8(-4.975,0.975) 9(-4.975,0.325) 10(-4.975,-0.325) 11(-4.975,-0.975) 12(-4.975,-1.625) 13(-4.975,-2.275) 14(-4.975,-2.925) 15(-4.975,-3.575) 16(-4.975,-4.225) 17(-4.975,-4.875) 18(-4.975,-5.525) 19(4.975,-5.525) 20(4.975,-4.875) 21(4.975,-4.225) 22(4.975,-3.575) 23(4.975,-2.925) 24(4.975,-2.275) 25(4.975,-1.625) 26(4.975,-0.975) 27(4.975,-0.325) 28(4.975,0.325) 29(4.975,0.975) 30(4.975,1.625) 31(4.975,2.275) 32(4.975,2.925) 33(4.975,3.575) 34(4.975,4.225) 35(4.975,4.875) 36(4.975,5.525)
  silkscreen extent -6.6,-6.47 3.67,6.47, body extent -6,-6.57 6,6.57, height 0.25
DWV0008A [mm] "SOIC, 8-Leads, Body 5.95x7.6mm (max), Pitch 1.27mm"
  rrect17% 1.8x0.6 smd: 1(-5.45,1.905) 2(-5.45,0.635) 3(-5.45,-0.635) 4(-5.45,-1.905) 5(5.45,-1.905) 6(5.45,-0.635) 7(5.45,0.635) 8(5.45,1.905)
  silkscreen extent -6.25,-2.95 2.98,2.95, body extent -5.77,-2.92 5.77,2.93, height 2.67
FCC_disclaimer [mm]
FP-GCM155R72A331KA37D_0402-MFG [mm]
  rrect25% 0.4x0.5 smd paste+0 mask+0: 1(-0.4,0) 2(0.4,0)
  silkscreen extent -0.53,-0.67 0.53,0.67, body extent -0.7,-0.38 0.7,0.38, height 0.25
FP-US1Q-TP_SMA-MFG [mm]
  rrect6% 1.78x2.16 smd paste+0 mask+0: 1(-2.025,0) 2(2.025,0)
  silkscreen extent -3.67,-1.46 2.37,1.46, body extent -3.02,-1.56 3.02,1.56, height 0.25
IEC_HighVoltage_Small [mm]
  silkscreen extent -2.72,-2.24 2.72,2.47
IEC_HotSurface_Small [mm]
  silkscreen extent -2.72,-2.36 2.72,2.35
Keystone5001 [mil] "For Keystone 500x miniature loop terminals"
  round 80 hole 40: 1(0,0)
  silkscreen extent -52,-52 52,52, body extent -49,-49 49,49, height 182
Keystone5002 [mil] "For Keystone 500x miniature loop terminals"
  round 80 hole 40: 1(0,0)
  silkscreen extent -52,-52 52,52, body extent -49,-49 49,49, height 182
PW0014A_N [mm] "TSOP, 14-Leads, Body 5x4.4mm, Pitch 0.65mm, IPC Medium Density"
  oval 1.4x0.45 smd: 1(-2.95,1.95) 2(-2.95,1.3) 3(-2.95,0.65) 4(-2.95,0) 5(-2.95,-0.65) 6(-2.95,-1.3) 7(-2.95,-1.95) 8(2.95,-1.95) 9(2.95,-1.3) 10(2.95,-0.65) 11(2.95,0) 12(2.95,0.65) 13(2.95,1.3) 14(2.95,1.95)
  silkscreen extent -3.4,-2.55 1.85,2.55, body extent -3.21,-2.5 3.21,2.5, height 1
SOT-23 [mm] "SOT23, 3-Leads, Body 2.9x1.3mm, Pitch 0.95mm, Lead Span 2.5mm, IPC Medium Density"
  rrect50% 1x0.6 smd: 1(-1.2,0.95) 2(-1.2,-0.95) 3(1.2,0)
  silkscreen extent -1.62,-1.5 0.7,1.5, body extent -1.16,-1.45 1.21,1.45, height 1
TESTPOINT_PIGTAIL [mil] "Pigtail"
  round 60 hole 42: 1(0,0)
  round 46 hole 32: 2(0,-200)
  silkscreen extent -50,-233 50,50
WEEE_Minimum [mm] "WEEElie bin"
  silkscreen extent -2.42,-4.38 2.52,2.65
WL-SMCW_GREEN [mm] "WURTH"
  rect 0.8x0.8 smd: 1(-0.8,0) 2(0.8,0)
  silkscreen extent -1.9,-0.8 1.2,0.8, body extent -0.85,-0.45 0.85,0.45, height 0.8
WL-SMCW_RED [mm] "WURTH"
  rect 0.8x0.8 smd: 1(-0.8,0) 2(0.8,0)
  silkscreen extent -1.9,-0.8 1.2,0.8, body extent -0.85,-0.45 0.85,0.45, height 0.8
Wurth_61300411021 [mm] "Header, 2.54 mm, 4x1, R/A, TH"
  rect 1.6x1.6 hole 1.1: 1(-3.81,0)
  round 1.6 hole 1.1: 2(-1.27,0) 3(1.27,0) 4(3.81,0)
  silkscreen extent -5.5,-4.04 5.08,-1.5, body extent -5.08,-10.04 5.08,0.32, height 2.55
Wurth_61301621021 [mm] "Header, 2.54mm, 8x2, R/A, TH"
  rrect50% 1.65x1.65 hole 1.1: 1(-1.27,8.89)
  round 1.65 hole 1.1: 2(1.27,8.89) 3(-1.27,6.35) 4(1.27,6.35) 5(-1.27,3.81) 6(1.27,3.81) 7(-1.27,1.27) 8(1.27,1.27) 9(-1.27,-1.27) 10(1.27,-1.27) 11(-1.27,-3.81) 12(1.27,-3.81) 13(-1.27,-6.35) 14(1.27,-6.35) 15(-1.27,-8.89) 16(1.27,-8.89)
  body extent -11.31,-10.16 1.59,10.16, height 5.08

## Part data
C101 C104 C109 C112 C201 C204: library part CMP-0007078-4, "CAP, CERM, 0.1 uF, 50 V, +/- 10%, X7R, AEC-Q200 Grade 1, 0603", Cap_Case=0603, Manufacturer=TDK, Supplier Part Number 1=445-5666-1-ND, TempCo=X7R, Tolerance_%=10%, Value1="0.0296 ohm", Value2=50V, ValueDisplayed=0.1uF
C102 C103 C110 C111 C203: library part CMP-0009122-1, "CAP, CERM, 2.2 uF, 50 V, +/- 10%, X7R, 1210", Cap_Case=1210_280, Manufacturer=TDK, Supplier Part Number 1=445-1431-1-ND, TempCo=X7R, Tolerance_%=10%, Value1="0.00536 ohm", Value2=50V, ValueDisplayed=2.2uF
C105 C113 C302 C315: library part CMP-0008959-2, "CAP, CERM, 22 uF, 10 V, +/- 10%, X7R, 1206", Cap_Case=1206, Manufacturer=MuRata, Supplier Part Number 1=490-5309-1-ND, TempCo=X7R, Tolerance_%=10%, Value1=Unknown, Value2=10V, ValueDisplayed=22uF
C106 C114 C206 C312 C326: library part CMP-0006629-2, "CAP, CERM, 0.1 uF, 10 V, +/- 10%, X7R, 0402", Cap_Case=0402, Manufacturer=MuRata, Supplier Part Number 1=GRM155R71A104KA01D-ND, TempCo=X7R, Tolerance_%=10%, Value1=Unknown, Value2=10V, ValueDisplayed=0.1uF
C107 C108 C115 C116 C207 C208: library part CMP-0006687-2, "CAP, CERM, 330 pF, 50 V, +/- 10%, X7R, 0402", Cap_Case=0402, Manufacturer=MuRata, Supplier Part Number 1=490-3247-1-ND, TempCo=X7R, Tolerance_%=10%, Value1=Unknown, Value2=50V, ValueDisplayed=330pF
C202: library part CMP-0007508-2, "CAP, CERM, 1 uF, 50 V, +/- 10%, X7R, 0603", Cap_Case=0603, Manufacturer="Taiyo Yuden", Supplier Part Number 1=587-3247-1-ND, TempCo=X7R, Tolerance_%=10%, Value1=Unknown, Value2=50V, ValueDisplayed=1uF
C205: library part CMP-0008721-2, "CAP, CERM, 15 uF, 10 V, +/- 20%, X7S, 1206", Cap_Case=1206_180, Manufacturer=TDK, Supplier Part Number 1=445-14815-1-ND, TempCo=X7S, Tolerance_%=20%, Value1="0.002667 ohm", Value2=10V, ValueDisplayed=15uF
C301 C309 C314 C323: library part CMP-0006815-4, "CAP, CERM, 0.1 uF, 10 V, +/- 10%, X7R, 0603", Cap_Case=0603, Manufacturer=AVX, Supplier Part Number 1=478-7939-1-ND, TempCo=X7R, Tolerance_%=10%, Value1=Unknown, Value2=10V, ValueDisplayed=0.1uF
C303 C305 C316 C318: library part CMP-0008876-2, "CAP, CERM, 0.1 uF, 50 V, +/- 10%, X7R, 1206", Cap_Case=1206, Manufacturer=MuRata, Supplier Part Number 1=490-1775-1-ND, TempCo=X7R, Tolerance_%=10%, Value1="0.01 ohm", Value2=50V, ValueDisplayed=0.1uF
C304 C317: library part CMP-0008992-2, "CAP, CERM, 1 uF, 50 V, +/- 10%, X7R, 1206", Cap_Case=1206, Manufacturer=MuRata, Supplier Part Number 1=GRM31MR71H105KA88L-ND, TempCo=X7R, Tolerance_%=10%, Value1=Unknown, Value2=50V, ValueDisplayed=1uF
C306 C319: library part CMP-0008954-3, "CAP, CERM, 10 uF, 50 V, +/- 10%, X5R, 1206", Cap_Case=1206, Manufacturer=MuRata, Supplier Part Number 1=490-5961-1-ND, TempCo=X5R, Tolerance_%=10%, Value1=Unknown, Value2=50V, ValueDisplayed=10uF
C307 C308 C320 C322 C410 C411: library part CMP-0006410-2, "CAP, CERM, 100 pF, 50 V, +/- 5%, C0G/NP0, 0402", Cap_Case=0402, Manufacturer=MuRata, Supplier Part Number 1=81-GRM1555C1H101JA1D, TempCo=C0G/NP0, Tolerance_%=5%, Value1=Unknown, Value2=50V, ValueDisplayed=100pF
C310 C324: library part CMP-0088316-1, "330pF ±10% 100V Ceramic Capacitor X7R 0402 (1005 Metric)", Digikey Part Number=490-17760-1-ND, Manufacturer=Murata, Mouser Part Number=81-GCM155R72A331KA7D, Operating Temperature Range="-55°C to +125°C", TempCo=15%, Temperature Characteristic=X7R, Tolerance_%=10%, ValueDisplayed=330pF
C311 C325: library part CMP-0006224-1, "CAP, CERM, 2200 pF, 10 V, +/- 10%, X7R, 0402", Cap_Case=0402, Manufacturer="Wurth Elektronik", Supplier Part Number 1=732-7503-1-ND, TempCo=X7R, Tolerance_%=10%, Value1=Unknown, Value2=10V, ValueDisplayed=2200pF
C313 C321: library part CMP-0008059-2, "CAP, CERM, 100 pF, 50 V, +/- 5%, C0G/NP0, 0805", Cap_Case=0805, Manufacturer=MuRata, Supplier Part Number 1=490-1615-1-ND, TempCo=C0G/NP0, Tolerance_%=5%, Value1=Unknown, Value2=50V, ValueDisplayed=100pF
C401 C402: library part CMP-0006233-2, "CAP, CERM, 100 pF, 25 V, +/- 5%, C0G/NP0, 0402", Cap_Case=0402, Manufacturer=Kemet, Supplier Part Number 1=399-1022-1-ND, TempCo=C0G/NP0, Tolerance_%=5%, Value1=Unknown, Value2=25V, ValueDisplayed=100pF
C403: library part CMP-0006837-4, "CAP, CERM, 0.1 uF, 50 V, +/- 10%, X7R, 0603", Cap_Case=0603, Manufacturer="Wurth Elektronik", TempCo=X7R, Tolerance_%=10%, Value1=Unknown, Value2=50V, ValueDisplayed=0.1uF
C404 C405 C406 C408 C412 C414: library part CMP-0006614-2, "CAP, CERM, 0.1 uF, 50 V, +/- 20%, X5R, 0402", Cap_Case=0402, Manufacturer=MuRata, Supplier Part Number 1=GRM155R61H104ME14D-ND, TempCo=X5R, Tolerance_%=20%, Value1=Unknown, Value2=50V, ValueDisplayed=0.1uF
C407 C409 C413 C415: library part CMP-0007007-1, "CAP, CERM, 10 uF, 25 V, +/- 20%, X5R, 0603", Cap_Case=0603, Manufacturer=TDK, Supplier Part Number 1=445-9015-1-ND, TempCo=X5R, Tolerance_%=20%, Value1="0.004639 ohm", Value2=25V, ValueDisplayed=10uF
D101 D102 D201: library part CMP-0002905-2, "LED, Green, SMD", Color=Green, Manufacturer="Wurth Elektronik", Value1=W, Value2=3.2V
D301 D302: library part CMP-0095286-1, "Diode Standard 1200 V 1A Surface Mount DO-214AC (SMA)", Digikey Part Number=US1Q-TPMSCT-ND, Forward Current=1A, Manufacturer=MCC, Max Surge Forward Current=30A, Mouser Part Number=833-US1Q-TP, Operating Temperature Range="-55°C to +150°C", Peak Reverse Current=5uA, ValueDisplayed=45pF
D401: library part CMP-0002947-2, "LED, Red, SMD", Color=Red, Manufacturer="Wurth Elektronik", Power_TotalModule=72mW, Supplier Part Number 1=732-4978-1-ND, Value1=0.072W, Value2=2V
D402 D403: library part CMP-0002905-1, "LED, Green, SMD", Color=Green, Manufacturer="Wurth Elektronik", Supplier Part Number 1=732-4971-1-ND, Value1=W, Value2=3.2V
FLT401 PWM401 PWM402 PWM403 PWM404 RDY401 RST401: library part CMP-0055139-1, "Test Point, Miniature, White, TH", Color=White, Manufacturer=Keystone, Supplier Part Number 1=36-5002-ND
J301 J302: library part CMP-0075320-1, "Receptacle, Ultra Miniature Coaxial, Male Pin, 50 ohm, SMT", Color=Beige, Manufacturer="Hirose Electric Co. Ltd.", Supplier Part Number 1=H122041-ND
J401: library part CMP-0081505-1, "Header, 2.54mm, 8x2, Gold, R/A, TH", Color=Black, Current_A=3A, Manufacturer="Wurth Elektronik", Supplier Part Number 1=732-5356-ND, Voltage_V=250V
J402 J403 J404 J405: library part CMP-0054797-1, "Header, 2.54 mm, 4x1, Gold, R/A, TH", Color=Black, Manufacturer="Wurth Elektronik", Supplier Part Number 1=732-5337-ND
LOGO101: library part CMP-0074835-1, "IEC 61010-1 High Voltage Warning"
Logo102: library part CMP-0074837-2, "IEC 61010-1 Hot Surface Warning", Manufacturer="Texas Instruments"
Logo103: library part CMP-0074769-1
Logo104: library part CMP-0074847-1, "FCC_disclaimer"
Q401: library part CMP-0000314-2, "Transistor, PNP, 65 V, 0.01 A, SOT-23", Manufacturer="Diodes Inc.", Supplier Part Number 1=BC856A-FDICT-ND, Value1="0.01 A"
R101 R110 R201: library part CMP-0020251-1, "RES, 65.7 k, 0.1%, 0.125 W, 0805", Manufacturer="Yageo America", Power_W=125mW, TempCo="25 ppm/C", Tolerance_%=0.1%, Value2=0.125W, Value_Code=65k7, ValueDisplayed=65.7k
R102 R111 R202: library part CMP-0026232-2, "RES, 2.21 k, 1%, 0.063 W, AEC-Q200 Grade 0, 0402", Manufacturer=Vishay-Dale, Power_W=63mW, Supplier Part Number 1=541-2.21KLCT-ND, TempCo="100 ppm/C", Tolerance_%=1%, Value2=0.063W, Value_Code=2k21, ValueDisplayed=2.21k
R103 R112 R203: library part CMP-0026699-1, "RES, 470, 1%, 0.1 W, AEC-Q200 Grade 0, 0402", Manufacturer=Panasonic, Power_W=100mW, Supplier Part Number 1=P470LCT-ND, TempCo="100 ppm/C", Tolerance_%=1%, Value2=0.1W, Value_Code=470R, ValueDisplayed=470
R104 R113 R204: library part CMP-0025950-3, "RES, 100 k, 1%, 0.063 W, AEC-Q200 Grade 0, 0402", Manufacturer=Vishay-Dale, Power_W=63mW, Supplier Part Number 1=541-100KLCT-ND, TempCo="100 ppm/C", Tolerance_%=1%, Value2=0.063W, Value_Code=100k
R105 R108 R114 R117 R205 R208 R303 R304 R305 R319 R320 R321: library part CMP-0025958-3, "RES, 10.0 k, 1%, 0.063 W, AEC-Q200 Grade 0, 0402", Manufacturer=Vishay-Dale, Power_W=63mW, Supplier Part Number 1=541-10.0KLCT-ND, TempCo="100 ppm/C", Tolerance_%=1%, Value2=0.063W, Value_Code=10k0, ValueDisplayed=10.0k
R106 R115 R206: library part CMP-0078244-2, "RES, 30.0 k, 1%, 0.063 W, AEC-Q200 Grade 0, 0402", Manufacturer=Vishay-Dale, Power_W=63mW, Supplier Part Number 1=541-30.0KLCT-ND, TempCo="100 ppm/C", Tolerance_%=1%, Value2=0.063W, Value_Code=30k0, ValueDisplayed=30.0k
R107 R116 R207: library part CMP-0026079-3, "RES, 1.21 k, 1%, 0.063 W, AEC-Q200 Grade 0, 0402", Manufacturer=Vishay-Dale, Power_W=63mW, Supplier Part Number 1=541-1.21KLCT-ND, TempCo="100 ppm/C", Tolerance_%=1%, Value2=0.063W, Value_Code=1k21, ValueDisplayed=1.21k
R109 R118 R209: library part CMP-0026718-1, "RES, 49.9 k, 1%, 0.063 W, 0402", Manufacturer=Rohm, Power_W=63mW, Supplier Part Number 1=RHM49.9KLCT-ND, TempCo="100 ppm/C", Tolerance_%=1%, Value2=0.063W, Value_Code=49k9, ValueDisplayed=49.9k
R301 R310 R315 R316 R317 R326 R415 R417: library part CMP-0025951-3, "RES, 100, 1%, 0.063 W, AEC-Q200 Grade 0, 0402", Manufacturer=Vishay-Dale, Power_W=63mW, Supplier Part Number 1=541-100LCT-ND, TempCo="100 ppm/C", Tolerance_%=1%, Value2=0.063W, Value_Code=100R, ValueDisplayed=100
R302 R318: library part CMP-0017916-2, "RES, 15.0 k, 1%, 0.25 W, 1206", Manufacturer="Yageo America", Power_W=250mW, Supplier Part Number 1=311-15.0KFRCT-ND, TempCo="100 ppm/C", Tolerance_%=1%, Value2=0.25W, Value_Code=15k0, ValueDisplayed=15.0k
R306 R322 R413 R414: library part CMP-0025963-3, "RES, 10.0, 1%, 0.063 W, AEC-Q200 Grade 0, 0402", Manufacturer=Vishay-Dale, Power_W=63mW, Supplier Part Number 1=541-10.0LCT-ND, TempCo="100 ppm/C", Tolerance_%=1%, Value2=0.063W, Value_Code=10R0, ValueDisplayed=10.0
R307 R308 R323 R324: library part CMP-0018648-3, "RES, 2.0, 5%, 0.25 W, AEC-Q200 Grade 0, 1206", Manufacturer=Vishay-Dale, Power_W=250mW, Supplier Part Number 1=541-2.0ECT-ND, TempCo="200 ppm/C", Tolerance_%=5%, Value2=0.25W, Value_Code=2R00, ValueDisplayed=2.0
R309 R325: library part CMP-0081723-1, "RES, 18.0 k, 1%, 0.1 W, AEC-Q200 Grade 0, 0402", Manufacturer=Panasonic, Power_W=100mW, Supplier Part Number 1=P18.0KLCT-ND, TempCo="100 ppm/C", Tolerance_%=1%, Value2=0.1W, Value_Code=18k0, ValueDisplayed=18.0k
R311 R327: library part CMP-0026162-2, "RES, 20.0 k, 1%, 0.063 W, AEC-Q200 Grade 0, 0402", Manufacturer=Vishay-Dale, Power_W=63mW, Supplier Part Number 1=541-20.0KLCT-ND, TempCo="100 ppm/C", Tolerance_%=1%, Value2=0.063W, Value_Code=20k0, ValueDisplayed=20.0k
R312 R328: library part CMP-0026227-2, "RES, 2.00 k, 1%, 0.063 W, AEC-Q200 Grade 0, 0402", Manufacturer=Vishay-Dale, Power_W=63mW, Supplier Part Number 1=541-2.00KLCT-ND, TempCo="100 ppm/C", Tolerance_%=1%, Value2=0.063W, Value_Code=2k00, ValueDisplayed=2.00k
R313 R329: library part CMP-0026822-3, "RES, 0, 5%, 0.063 W, AEC-Q200 Grade 0, 0402", Manufacturer=Vishay-Dale, Power_W=63mW, Supplier Part Number 1=541-0.0JCT-ND, TempCo="200 ppm/C", Tolerance_%=5%, Value2=0.063W, Value_Code=0000, ValueDisplayed=0
R314 R330: library part CMP-0026513-2, "RES, 6.19 k, 1%, 0.063 W, AEC-Q200 Grade 0, 0402", Manufacturer=Vishay-Dale, Power_W=63mW, Supplier Part Number 1=541-6.19KLCT-ND, TempCo="100 ppm/C", Tolerance_%=1%, Value2=0.063W, Value_Code=6k19, ValueDisplayed=6.19k
R401: library part CMP-0022691-3, "RES, 20.0 k, 1%, 0.1 W, AEC-Q200 Grade 0, 0603", Manufacturer=Panasonic, Power_W=100mW, Supplier Part Number 1=P20.0KHCT-ND, TempCo="100 ppm/C", Tolerance_%=1%, Value2=0.1W, Value_Code=20k0, ValueDisplayed=20.0k
R402: library part CMP-0023219-5, "RES, 620, 1%, 0.1 W, 0603", Manufacturer=Yageo, Power_W=100mW, Supplier Part Number 1=311-620HRCT-ND, TempCo="100 ppm/C", Tolerance_%=1%, Value2=0.1W, Value_Code=620R, ValueDisplayed=620
R403: library part CMP-0024061-1, "RES, 2.18 k, 0.1%, 0.1 W, 0603", Manufacturer="Yageo America", Power_W=100mW, TempCo="25 ppm/C", Tolerance_%=0.1%, Value2=0.1W, Value_Code=2k18, ValueDisplayed=2.18k
R404 R408 R409 R410 R411 R412: library part CMP-0021998-4, "RES, 10.0 k, 1%, 0.1 W, AEC-Q200 Grade 0, 0603", Manufacturer=Vishay-Dale, Power_W=100mW, Supplier Part Number 1=541-10.0KHCT-ND, TempCo="100 ppm/C", Tolerance_%=1%, Value2=0.1W, Value_Code=10k0, ValueDisplayed=10.0k
R405: library part CMP-0026833-3, "RES, 120, 5%, 0.063 W, AEC-Q200 Grade 0, 0402", Manufacturer=Vishay-Dale, Power_W=63mW, Supplier Part Number 1=541-120JCT-ND, TempCo="200 ppm/C", Tolerance_%=5%, Value2=0.063W, Value_Code=120R, ValueDisplayed=120
R406: library part CMP-0022751-4, "RES, 10.0, 1%, 0.1 W, 0603", Manufacturer=Yageo, Power_W=100mW, Supplier Part Number 1=311-10.0HRCT-ND, TempCo="100 ppm/C", Tolerance_%=1%, Value2=0.1W, Value_Code=10R0, ValueDisplayed=10.0
R407: library part CMP-0025874-4, "RES, 0, 5%, 0.1 W, AEC-Q200 Grade 0, 0603", Manufacturer=Panasonic, Power_W=100mW, Supplier Part Number 1=P0.0GCT-ND, TempCo="600 ppm/C", Tolerance_%=5%, Value2=0.1W, Value_Code=0000, ValueDisplayed=0
R416 R418 R419 R420: library part CMP-0018270-2, "RES, 3.30, 1%, 0.25 W, 1206", Manufacturer="Yageo America", Power_W=250mW, Supplier Part Number 1=311-3.30FRCT-ND, TempCo="200 ppm/C", Tolerance_%=1%, Value2=0.25W, Value_Code=3R30, ValueDisplayed=3.30
R421 R422: library part CMP-0086358-1, "RES, 0, 0%, 0.25 W, AEC-Q200 Grade 0, 0603", Manufacturer=Rohm, Power_W=250mW, Tolerance_%=0%, Value2=0.25W, Value_Code=0000, ValueDisplayed=0
TP301 TP303 TP401: library part CMP-0055138-2, "Test Point, Miniature, Black, TH", Color=Black, Manufacturer="Keystone Electronics", Supplier Part Number 1=36-5001-ND
TP302 TP304: library part CMP-0003907-1, "PIGTAIL", Manufacturer="Texas Instruments", PartNumber=TESTPOINT_PIGTAIL
U101 U102 U201: library part CMP-0089786-7, "2W, 24V-Vin, 25V-Vout, High-Efficiency, >2. 5 kVRMS Isolated DC-DC Converter", Manufacturer="Texas Instruments", Max Supply Voltage=27V, Min Supply Voltage=21V, Operating Temperature Range="-40°C to +150°C", Output Voltage=18-25/2.5-25V
U301 U302: library part CMP-0080534-2, "Single Channel Isolated Gate Driver for SiC/IGBT with Advanced Protection and High-CMTI, DW0016B (SOIC-16)", Alternate Manufacturer="Texas Instruments", Alternate PartNumber=UCC21710QDWRQ1
U401: library part CMP-0066280-1, "Quadruple Bus Buffer Gate with 3-State Outputs, PW0014A (TSSOP-14)", Alternate Manufacturer="Texas Instruments", Alternate PartNumber=SN74LVC126APW
U402 U403: library part CMP-0078838-1, "5-kVRMS Single-Channel Isolated Gate Drivers, DWV0008A (SOIC-8)", Alternate Manufacturer="Texas Instruments", Alternate PartNumber=UCC5320SCDWVR

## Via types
v1: diameter 0.762, hole 0.305, Top Layer to Bottom Layer, tented top, 126 vias
v2: diameter 0.61, hole 0.305, Top Layer to Bottom Layer, tented top, 13 vias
